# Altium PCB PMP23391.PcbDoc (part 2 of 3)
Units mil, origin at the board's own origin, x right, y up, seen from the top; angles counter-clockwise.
Board outline 5500 x 3250 mil, 2 copper layers (Top Layer, Bottom Layer), stack 62 mil thick; 163 components, 101 nets, 543 pads, 307 vias.
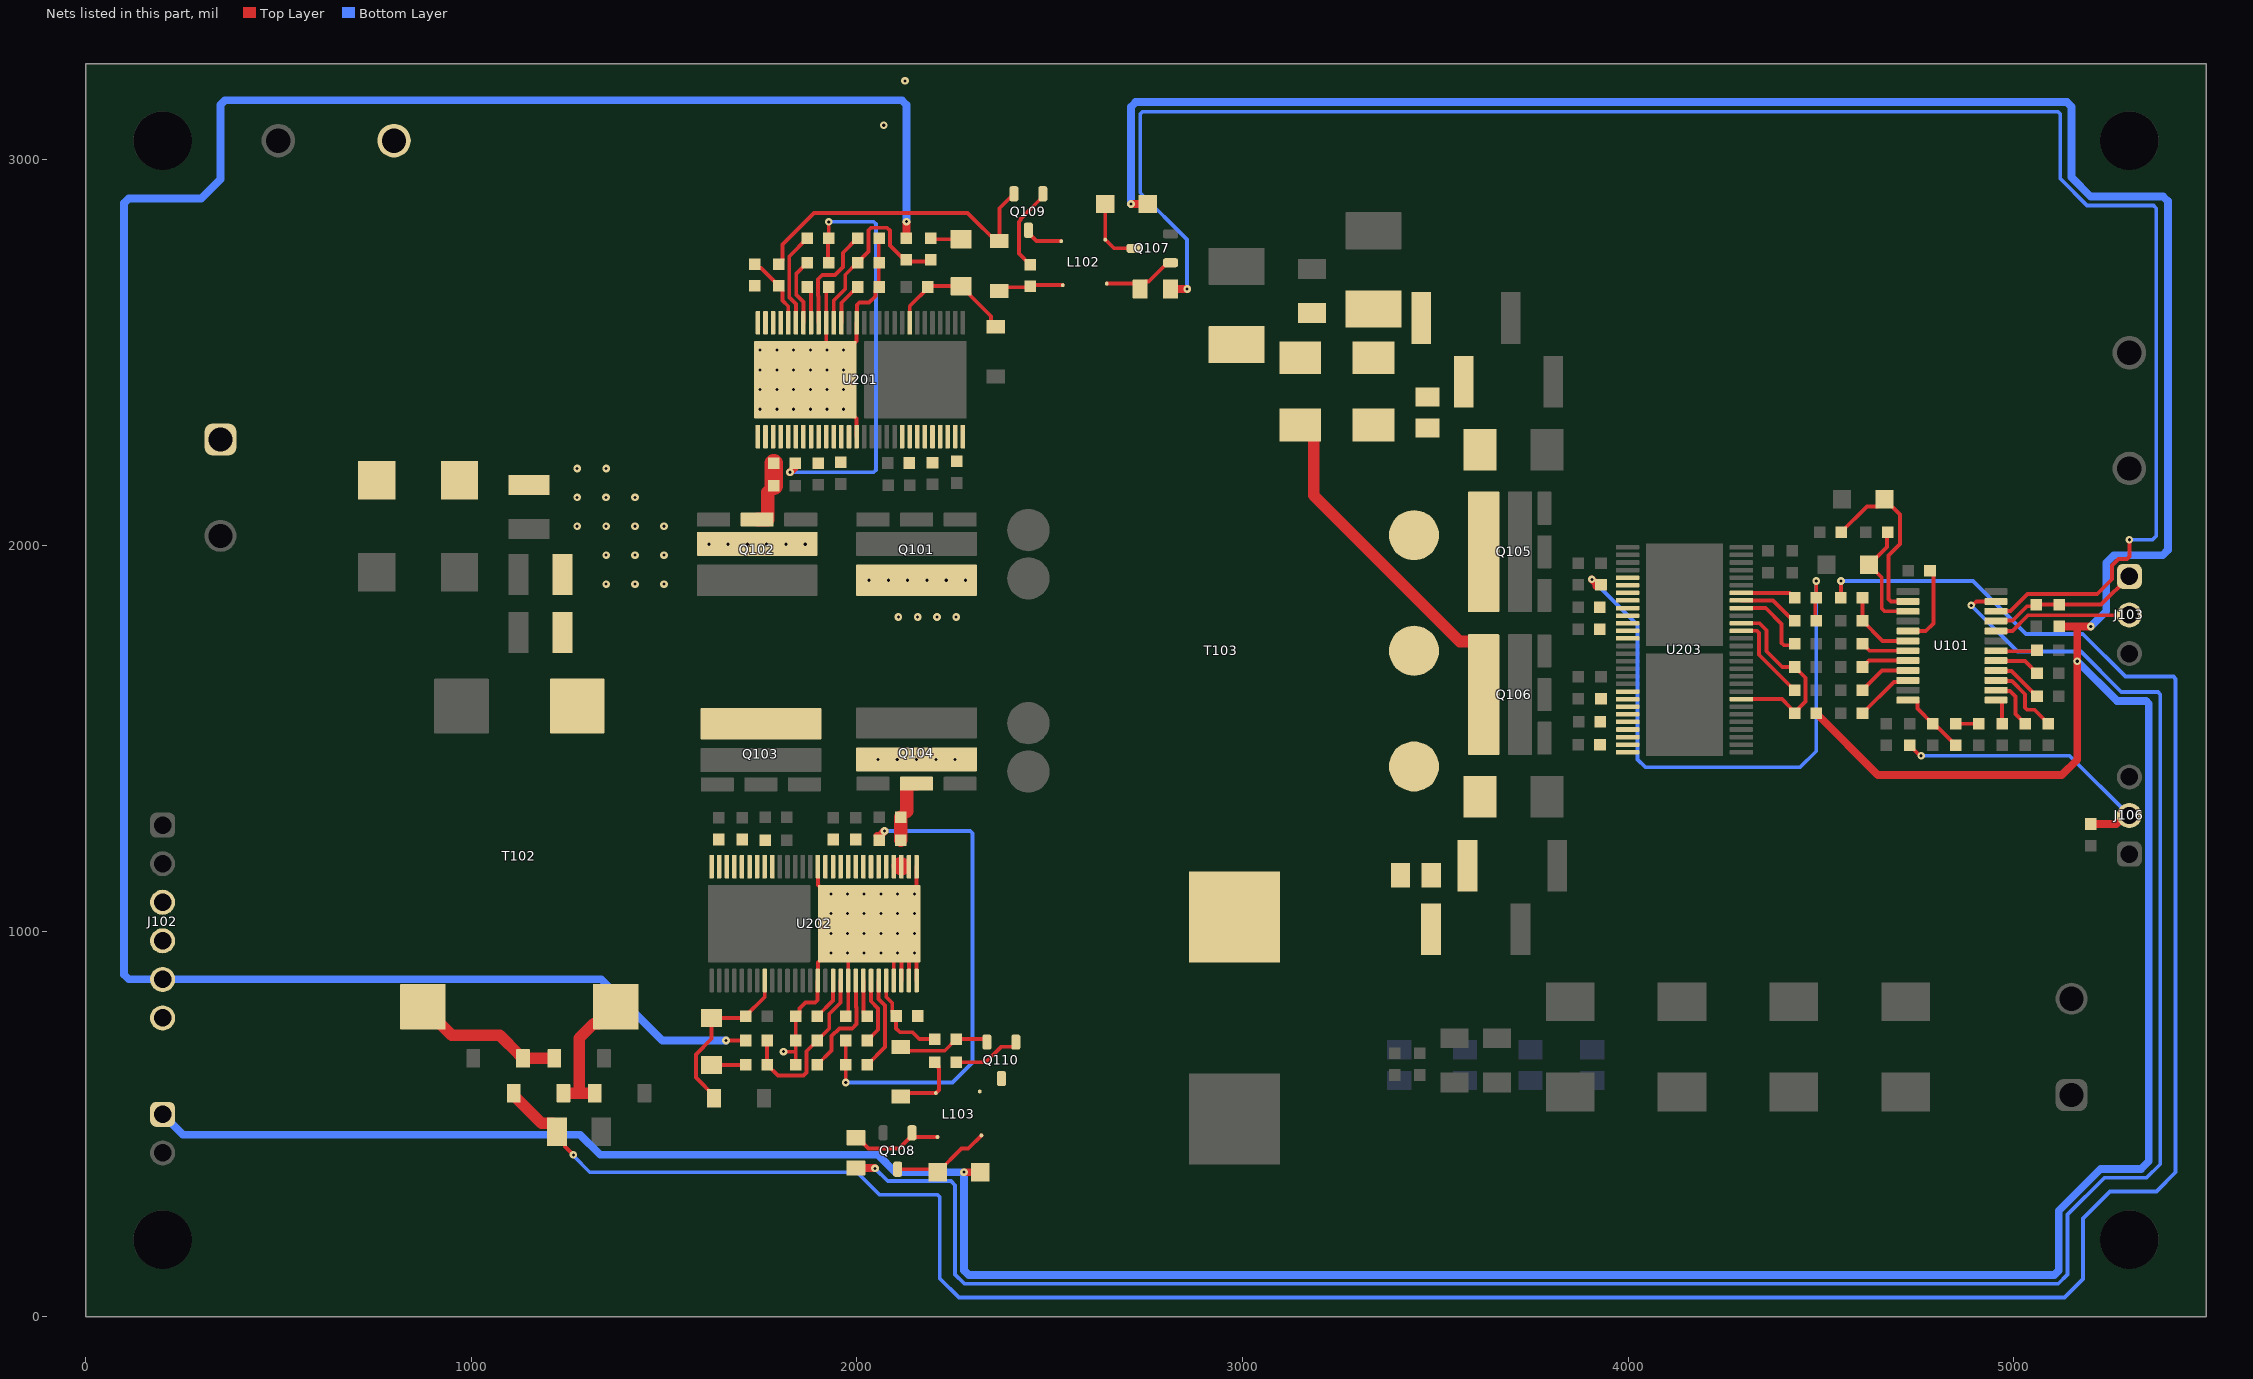
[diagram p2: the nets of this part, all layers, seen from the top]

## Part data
C101 C115 C116 C201 C202 C204 C206 C207 C209 C211 C212: library part CMP-0007405-5, "CAP, CERM, 1 uF, 25 V, +/- 10%, X7R, 0603", Cap_Case=0603, Manufacturer=MuRata, Supplier Part Number 1=490-5307-1-ND, TempCo=X7R, Tolerance_%=10%, Value1=Unknown, Value2=25V, ValueDisplayed=1uF
C102 C103: library part CMP-0011753-2, "CAP, TA, 22 uF, 50 V, +/- 10%, 0.5 ohm, SMD", Cap_Case=7343-43, Manufacturer=Kemet, Supplier Part Number 1=399-10275-1-ND, Tolerance_%=10%, Value1="0.5 ohm", Value2=50V, ValueDisplayed=22uF
C104 C205 C210 C213 C214: library part CMP-0007499-4, "CAP, CERM, 2.2 uF, 16 V, +/- 10%, X7R, 0603", Cap_Case=0603, Manufacturer=MuRata, Supplier Part Number 1=81-GRM188Z71C225KE3D, TempCo=X7R, Tolerance_%=10%, Value1=Unknown, Value2=16V, ValueDisplayed=2.2uF
C105: library part CMP-0007425-5, "CAP, CERM, 5600 pF, 25 V, +/- 10%, X7R, 0603", Cap_Case=0603, Manufacturer=MuRata, Supplier Part Number 1=GRM188R71E562KA01D-ND, TempCo=X7R, Tolerance_%=10%, Value1=Unknown, Value2=25V, ValueDisplayed=5600pF
C106: library part CMP-0084679-1, "CAP, CERM, 0.1 µF, 25 V,+/- 10%, X7R, AEC-Q200 Grade 1, 0603", Cap_Case=0603, Manufacturer=MuRata, TempCo=X7R, Tolerance_%=10%, Value2=25V, ValueDisplayed=0.1µF
C107 C108: library part CMP-0860266-1, "CAP, CERM, 10 µF, 50 V,+/- 10%, X8L, AEC-Q200 Grade 0, 1210", Cap_Case=1210, Manufacturer=MuRata, TempCo=X8L, Tolerance_%=10%, Value2=50V, ValueDisplayed=10µF
C109: library part CMP-0007138-4, "CAP, CERM, 0.47 uF, 16 V, +/- 10%, X7R, AEC-Q200 Grade 1, 0603", Cap_Case=0603, Manufacturer=MuRata, Supplier Part Number 1=490-4775-1-ND, TempCo=X7R, Tolerance_%=10%, Value1=Unknown, Value2=16V, ValueDisplayed=0.47uF
C110: library part CMP-0084283-1, "CAP, CERM, 10 pF, 100 V,+/- 5%, C0G/NP0, AEC-Q200 Grade 1, 0603", Cap_Case=0603, Manufacturer=MuRata, TempCo=C0G/NP0, Tolerance_%=5%, Value2=100V, ValueDisplayed=10pF
C111: library part CMP-0007427-5, "CAP, CERM, 6800 pF, 25 V, +/- 10%, X7R, 0603", Cap_Case=0603, Manufacturer=MuRata, Supplier Part Number 1=81-GRM18R71E682KA01D, TempCo=X7R, Tolerance_%=10%, Value1=Unknown, Value2=25V, ValueDisplayed=6800pF
C112: library part CMP-0007179-4, "CAP, CERM, 120 pF, 50 V, +/- 5%, C0G/NP0, 0603", Cap_Case=0603, Manufacturer=MuRata, Supplier Part Number 1=490-1429-1-ND, TempCo=C0G/NP0, Tolerance_%=5%, Value1=Unknown, Value2=50V, ValueDisplayed=120pF
C113 C114 C305 C306: library part CMP-0007171-4, "CAP, CERM, 100 pF, 50 V, +/- 5%, C0G/NP0, 0603", Cap_Case=0603, Manufacturer=MuRata, Supplier Part Number 1=490-1427-1-ND, TempCo=C0G/NP0, Tolerance_%=5%, Value1=Unknown, Value2=50V, ValueDisplayed=100pF
C117 C118: library part CMP-0008098-2, "CAP, CERM, 1200 pF, 100 V, +/- 5%, C0G/NP0, 0805", Cap_Case=0805, Manufacturer=MuRata, Supplier Part Number 1=GRM2165C2A122JA01D-ND, TempCo=C0G/NP0, Tolerance_%=5%, Value1=Unknown, Value2=100V, ValueDisplayed=1200pF
C119 C120: library part CMP-0082252-1, "CAP, CERM, 10 µF, 25 V,+/- 20%, X7R, AEC-Q200 Grade 1, 1206", Cap_Case=1206, Manufacturer=MuRata, Supplier Part Number 1=490-6519-1-ND, TempCo=X7R, Tolerance_%=20%, Value2=25V, ValueDisplayed=10µF
C121 C123 C124 C125: library part CMP-0012041-2, "CAP, TA, 100 uF, 25 V, +/- 10%, 0.1 ohm, SMD", Cap_Case=V, Manufacturer=AVX, Supplier Part Number 1=478-3104-1-ND, Tolerance_%=10%, Value1="0.1 ohm", Value2=25V, ValueDisplayed=100uF
C122: library part CMP-0008881-2, "CAP, CERM, 0.1 uF, 100 V, +/- 10%, X7R, 1206", Cap_Case=1206, Manufacturer=MuRata, Supplier Part Number 1=490-3364-1-ND, TempCo=X7R, Tolerance_%=10%, Value1=Unknown, Value2=100V, ValueDisplayed=0.1uF
C203 C208: library part CMP-0079602-1, "CAP, CERM, 0.1 µF, 50 V,+/- 10%, X7R, AEC-Q200 Grade 1, 0603", Cap_Case=0603, Manufacturer=Kemet, Supplier Part Number 1=399-6856-1-ND, TempCo=X7R, Tolerance_%=10%, Value2=50V, ValueDisplayed=0.1µF
C301 C302 C303 C304: library part CMP-0008346-3, "CAP, CERM, 4.7 uF, 25 V, +/- 10%, X7R, 0805", Cap_Case=0805, Manufacturer=MuRata, Supplier Part Number 1=490-9962-1-ND, TempCo=X7R, Tolerance_%=10%, Value1=Unknown, Value2=25V, ValueDisplayed=4.7uF
D101 D102 D103 D104: library part CMP-0090343-1, "Diode Schottky 100V 250mA (DC) Surface Mount SOD-123", Digikey Part Number=1727-7326-1-ND, Forward Current=250mA, Manufacturer=Nexperia, Max Surge Forward Current=2.5A, Mouser Part Number=841-BAT46GWJ, Operating Temperature Range="to +150°C", Peak Reverse Current=2uA, ValueDisplayed=39pF
D105 D108 D111 D112: library part CMP-0080763-2, "Diode, Schottky, 40 V, 3 A, AEC-Q101, SOD-123W", Manufacturer=Nexperia, Value1=3A, Value2=0.54V
D106 D107 D109 D110: library part CMP-0028521-2, "Diode, Schottky, 100 V, 1 A, SMB", Manufacturer="ON Semiconductor", Value1=1A, Value2=0.75V
D113 D114: library part CMP-0076974-2, "Diode, Switching, 100 V, 0.15 A, SOD-123", Manufacturer="Micro Commercial Components", Value1=0.15A, Value2=1.25V
D201 D203: library part CMP-0095320-1, "Diode Schottky 200 V 1A Surface Mount SOD-123W", Digikey Part Number=SS1H20LWRVGCT-ND, Forward Current=1A, Manufacturer="Taiwan Semiconductor", Max Surge Forward Current=30A, Mouser Part Number=821-SS1H20LW, Operating Temperature Range="-55°C to +175°C", Peak Reverse Current=0.1mA
D202 D204: library part CMP-0005752-4, "Diode, Zener, 13 V, 500 mW, SOD-123", Manufacturer="Diodes Inc.", Power_W=500mW, Value1=0.5W
H201 H202 H203 H204: library part CMP-0003690-1, Manufacturer=Keystone, Supplier Part Number 1=36-4824-ND
J101 J105: library part CMP-0075360-1, "Terminal Block, 6.35mm, 2x1, TH", Color=Green, Current_A=30A, Manufacturer="On-Shore Technology", Supplier Part Number 1=ED2675-ND, Voltage_V=300V
J102: library part CMP-0054801-2, "Header, 2.54 mm, 6x1, Gold, TH", Color=Black, Manufacturer="Wurth Elektronik", Supplier Part Number 1=732-5319-ND
J103 J106: library part CMP-0054796-4, "Header, 2.54 mm, 3x1, Gold, TH", Manufacturer="Wurth Elektronik", Supplier Part Number 1=732-5316-ND
J104: library part CMP-0054794-2, "Header, 2.54 mm, 2x1, Gold, TH", Color=Black, Manufacturer="Wurth Elektronik", Supplier Part Number 1=732-5315-ND
L101: library part CMP-0064040-1, "Inductor, Shielded Drum Core, WE-Superflux200, 1.3 uH, 34.5 A, 0.0009 ohm, SMD", Manufacturer="Wurth Elektronik", Supplier Part Number 1=732-2168-1-ND, Value1="0.0009 ohm", Value2=34.5A, ValueDisplayed=1.3uH
L102 L103: library part CMP-0012812-2, "Coupled inductor, 22 uH, 0.7 A, 1.63 ohm, TH", Manufacturer=Coilcraft, Supplier Part Number 1=994-LPD4012-333MRB, ValueDisplayed=22uH
Logo101: library part CMP-0074837-2, "IEC 61010-1 Hot Surface Warning", Manufacturer="Texas Instruments"
Logo201: library part CMP-0074769-1
Logo202: library part CMP-0074847-1, "FCC_disclaimer"
Logo203: library part CMP-0074836-1, "IEC 61010-1 Caution Warning"
Q101 Q102 Q103 Q104 Q105 Q106: library part CMP-0047628-1, "MOSFET N-Channel 100 V 80A (Tc) Surface Mount 5-SMD", Digikey Part Number=4107-EPC7018GC-ND, Drain To Source Breakdown Voltage=100V, Input Capacitace At Vds="1240pF @ 50V", Manufacturer="EPC Space", Operating Temperature Range="-55°C to +150°C", Pulse Drain Current=345A
Q107 Q108: library part CMP-0000755-1, "MOSFET, N-CH, 50 V, 0.22 A, SOT-23", Alternate Manufacturer=None, Manufacturer="Fairchild Semiconductor", Supplier Part Number 1=BSS138CT-ND, Value2="1.7 nC"
Q109 Q110: library part CMP-0000331-2, "Transistor, PNP, 60 V, 0.8 A, SOT-23", Manufacturer="Fairchild Semiconductor", Supplier Part Number 1=MMBT2907AFSCT-ND, Value1="0.8 A", Value2=300
R101: library part CMP-0022052-4, "RES, 147 k, 1%, 0.1 W, AEC-Q200 Grade 0, 0603", Manufacturer=Vishay-Dale, Power_W=100mW, Supplier Part Number 1=541-147KHCT-ND, TempCo="100 ppm/C", Tolerance_%=1%, Value2=0.1W, Value_Code=147k
R102: library part CMP-0022589-4, "RES, 75.0 k, 1%, 0.1 W, AEC-Q200 Grade 0, 0603", Manufacturer=Vishay-Dale, Power_W=100mW, Supplier Part Number 1=541-75.0KHCT-ND, TempCo="100 ppm/C", Tolerance_%=1%, Value2=0.1W, Value_Code=75k0, ValueDisplayed=75.0k
R103: library part CMP-0016768-3, "RES, 1.69, 1%, 0.25 W, AEC-Q200 Grade 0, 1206", Manufacturer=Vishay-Dale, Power_W=250mW, Supplier Part Number 1=541-1.69FFCT-ND, TempCo="100 ppm/C", Tolerance_%=1%, Value2=0.25W, Value_Code=1R69, ValueDisplayed=1.69
R104 R230: library part CMP-0022447-4, "RES, 49.9 k, 1%, 0.1 W, AEC-Q200 Grade 0, 0603", Manufacturer=Vishay-Dale, Power_W=100mW, Supplier Part Number 1=541-49.9KHCT-ND, TempCo="100 ppm/C", Tolerance_%=1%, Value2=0.1W, Value_Code=49k9, ValueDisplayed=49.9k
R105: library part CMP-0022903-4, "RES, 205 k, 1%, 0.1 W, 0603", Manufacturer=Yageo, Power_W=100mW, Supplier Part Number 1=311-205KHRCT-ND, TempCo="100 ppm/C", Tolerance_%=1%, Value2=0.1W, Value_Code=205k
R106: library part CMP-0025736-4, "RES, 1.0 M, 5%, 0.1 W, AEC-Q200 Grade 0, 0603", Manufacturer=Vishay-Dale, Power_W=100mW, Supplier Part Number 1=541-1.0MGCT-ND, TempCo="200 ppm/C", Tolerance_%=5%, Value2=0.1W, Value_Code=1M00, ValueDisplayed=1.0M
R107 R109 R201 R202 R214 R216 R227 R229: library part CMP-0025697-4, "RES, 0, 5%, 0.1 W, AEC-Q200 Grade 0, 0603", Manufacturer=Vishay-Dale, Power_W=100mW, Supplier Part Number 1=541-0.0GCT-ND, TempCo="200 ppm/C", Tolerance_%=5%, Value2=0.1W, Value_Code=0000, ValueDisplayed=0
R108: library part CMP-0015178-2, "RES, 0.3, 1%, 0.5 W, 1210", Manufacturer=Rohm, Power_W=500mW, Supplier Part Number 1=RHM.30SCT-ND, TempCo="200 ppm/C", Tolerance_%=1%, Value2=0.5W, Value_Code=R300, ValueDisplayed=0.3
R110: library part CMP-0022347-4, "RES, 34.8 k, 1%, 0.1 W, AEC-Q200 Grade 0, 0603", Manufacturer=Vishay-Dale, Power_W=100mW, Supplier Part Number 1=541-34.8KHCT-ND, TempCo="100 ppm/C", Tolerance_%=1%, Value2=0.1W, Value_Code=34k8, ValueDisplayed=34.8k
R111: library part CMP-0022126-4, "RES, 1.50 k, 1%, 0.1 W, AEC-Q200 Grade 0, 0603", Manufacturer=Vishay-Dale, Power_W=100mW, Supplier Part Number 1=541-1.50KHCT-ND, TempCo="100 ppm/C", Tolerance_%=1%, Value2=0.1W, Value_Code=1k50, ValueDisplayed=1.50k
R112: library part CMP-0022324-4, "RES, 30.1 k, 1%, 0.1 W, AEC-Q200 Grade 0, 0603", Manufacturer=Vishay-Dale, Power_W=100mW, Supplier Part Number 1=541-30.1KHCT-ND, TempCo="100 ppm/C", Tolerance_%=1%, Value2=0.1W, Value_Code=30k1, ValueDisplayed=30.1k
R113 R114 R204 R217: library part CMP-0025700-4, "RES, 100, 5%, 0.1 W, AEC-Q200 Grade 0, 0603", Manufacturer=Vishay-Dale, Power_W=100mW, Supplier Part Number 1=541-100GCT-ND, TempCo="200 ppm/C", Tolerance_%=5%, Value2=0.1W, Value_Code=100R, ValueDisplayed=100
R115 R116: library part CMP-0020803-2, "RES, 0, 5%, 0.125 W, 0805", Manufacturer="Yageo America", Power_W=125mW, Supplier Part Number 1=311-0.0ARCT-ND, TempCo="200 ppm/C", Tolerance_%=5%, Value2=0.125W, Value_Code=0000, ValueDisplayed=0
R117 R118 R119 R120: library part CMP-0015945-3, "RES, 33, 5%, 1 W, AEC-Q200 Grade 0, 2512", Manufacturer=Vishay-Dale, Power_W=1W, Supplier Part Number 1=541-33XCT-ND, TempCo="200 ppm/C", Tolerance_%=5%, Value_Code=33R0, ValueDisplayed=33
R121 R301: library part CMP-0122385-1, "10 kOhms ±1% 2W Chip Resistor 2512 (6432 Metric) Current Sense Thick Film", Digikey Part Number=118-CRM2512-FX-1002ELFCT-ND, Manufacturer=Bourns, Mouser Part Number=652-CRM2512FX1002ELF, Operating Temperature Range="-55°C to +155°C", Power_W=2W, TempCo=100ppm/°C, Tolerance_%=1%
R122 R123 R206 R212 R213 R219 R225 R226 R228 R235 R236: library part CMP-0021998-4, "RES, 10.0 k, 1%, 0.1 W, AEC-Q200 Grade 0, 0603", Manufacturer=Vishay-Dale, Power_W=100mW, Supplier Part Number 1=541-10.0KHCT-ND, TempCo="100 ppm/C", Tolerance_%=1%, Value2=0.1W, Value_Code=10k0, ValueDisplayed=10.0k
R124: library part CMP-0022003-4, "RES, 10.0, 1%, 0.1 W, AEC-Q200 Grade 0, 0603", Manufacturer=Vishay-Dale, Power_W=100mW, Supplier Part Number 1=541-10.0HCT-ND, TempCo="100 ppm/C", Tolerance_%=1%, Value2=0.1W, Value_Code=10R0, ValueDisplayed=10.0
R125: library part CMP-0022012-4, "RES, 115 k, 1%, 0.1 W, AEC-Q200 Grade 0, 0603", Manufacturer=Vishay-Dale, Power_W=100mW, Supplier Part Number 1=541-115KHCT-ND, TempCo="100 ppm/C", Tolerance_%=1%, Value2=0.1W, Value_Code=115k
R126: library part CMP-0022559-4, "RES, 6.19 k, 1%, 0.1 W, AEC-Q200 Grade 0, 0603", Manufacturer=Vishay-Dale, Power_W=100mW, Supplier Part Number 1=541-6.19KHCT-ND, TempCo="100 ppm/C", Tolerance_%=1%, Value2=0.1W, Value_Code=6k19, ValueDisplayed=6.19k
R203 R205 R215 R218: library part CMP-0021990-4, "RES, 100 k, 1%, 0.1 W, AEC-Q200 Grade 0, 0603", Manufacturer=Vishay-Dale, Power_W=100mW, Supplier Part Number 1=541-100KHCT-ND, TempCo="100 ppm/C", Tolerance_%=1%, Value2=0.1W, Value_Code=100k
R207 R220: library part CMP-0022732-2, "RES, 2.00, 1%, 0.125 W, 0603", Manufacturer=Vishay/Beyschlag, Power_W=125mW, Supplier Part Number 1=MCT06030C2008FP500-ND, TempCo="50 ppm/C", Tolerance_%=1%, Value2=0.125W, Value_Code=2R00, ValueDisplayed=2.00
R208 R209 R210 R211 R221 R222 R223 R224 R231 R232 R233 R234: library part CMP-0022311-4, "RES, 2.49, 1%, 0.1 W, AEC-Q200 Grade 0, 0603", Manufacturer=Vishay-Dale, Power_W=100mW, Supplier Part Number 1=541-2.49HHCT-ND, TempCo="100 ppm/C", Tolerance_%=1%, Value2=0.1W, Value_Code=2R49, ValueDisplayed=2.49
T102: library part CMP-0122471-1, "Current Transformer 1:50", Manufacturer="Payton Planar", Operating Temperature Range=to
T103: library part CMP-0122726-1, "Transformer Vin-22-36V/500KHz/Full-Bridge, Vo=12V/26A Isolation=1500V, T/R=3:2", Manufacturer=Coilcraft, Operating Temperature Range=to, Voltage_Isolation_Vrms=1.5kV
TP101 TP103: library part CMP-0055147-2, "Test Point, Multipurpose, Red, TH", Color=Red, Manufacturer="Keystone Electronics", Supplier Part Number 1=36-5010-ND
TP102 TP104: library part CMP-0055148-2, "Test Point, Multipurpose, Black, TH", Color=Black, Manufacturer="Keystone Electronics", Supplier Part Number 1=36-5011-ND
U101: library part CMP-0092938-1, Manufacturer="Texas Instruments", Operating Temperature Range=to
U201 U202 U203: library part CMP-0120202-4, Manufacturer="Texas Instruments", Operating Temperature Range=to

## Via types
v1: diameter 20, hole 8, Top Layer to Bottom Layer, 211 vias
v2: diameter 19.68, hole 7.87, Top Layer to Bottom Layer, tented both sides, 96 vias

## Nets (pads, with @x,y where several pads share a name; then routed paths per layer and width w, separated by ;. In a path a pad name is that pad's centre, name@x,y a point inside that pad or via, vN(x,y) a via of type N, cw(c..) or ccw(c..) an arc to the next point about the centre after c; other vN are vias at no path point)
+12Vp: J102.5 R201.1 R214.1 | length 6287.4
  Top Layer w10: v1(1660.91,716.59) R214.1@1711.65,716.59
  Top Layer w20: R201.1@2128.76,2796.84 v1(2128.76,2839.87)
  Bottom Layer w20: v1(1660.91,716.59) 1496.05,716.59 1337.64,875 J102.5@200,875 111.72,875 100,886.72 100,2888.28 111.72,2900 300,2900 350,2950 350,3143.28 361.72,3155 2117.04,3155 2128.76,3143.28 v1(2128.76,2839.87)
+12Vs: D111.1 D112.1 J104.1 R107.2 R227.1 | length 12792.8
  Top Layer w20: v1(2278.28,375) D112.1@2320.12,375 ; v1(2711.3,2885.7) D111.1@2754.33,2885.7 ; R227.1@4488,1565 4648,1405 5125,1405 5165,1445 v1(5165,1700) 5165,1790 ; R107.2@5119.48,1790 5165,1790 ; v1(5200,1790) 5165,1790
  Bottom Layer w20: J104.1@200,525 252.79,472.21 1282.21,472.21 1334.42,420 2055,420 2100,375 v1(2278.28,375) 2278.28,120.18 2289.99,108.46 5105.41,108.46 5117.13,120.18 5117.13,274.81 5225.78,383.46 5330.49,383.46 5350.35,403.32 5350.35,1590.06 5343.28,1597.13 5267.87,1597.13 v1(5165,1700) ; v1(2711.3,2885.7) 2711.3,3138.28 2723.01,3150 5138.28,3150 5150,3138.28 5150,2955 5200,2905 5388.28,2905 5400,2893.28 5400,1988.56 5386.44,1975 5260,1975 5240,1955 5240,1830 v1(5200,1790)
NetC101_1: C101.1 J103.1 R107.1 U101.9 | length 395.8
  Top Layer w10: U101.9@4952.77,1802.86 4955.71,1805.8 4997.62,1805.8 5034.45,1842.64 5054.35,1842.64 C101.1@5058.6,1846.89 R107.1@5118.6,1846.89 5226.89,1846.89 J103.1@5300,1920
NetC104_2: C104.2 U101.17 | length 214.9
  Top Layer w10: U101.17@4725.83,1778.39 4772.14,1778.39 4792,1798.24 4792,1926 C104.2@4783,1935
NetC105_2: C105.2 U101.5 | length 120.9
  Top Layer w10: U101.5@4952.77,1700.5 5028.98,1700.5 C105.2@5060.6,1668.89
NetC106_1: C106.1 U101.22 | length 153.2
  Top Layer w9.84: C106.1@4608,1565 4689.5,1646.5 4721.89,1646.5 U101.22@4725.83,1650.43
NetC109_2: C109.2 U101.20 | length 124.7
  Top Layer w10: C109.2@4608,1685 4624.61,1701.61 U101.20@4725.83,1701.61
NetC110_1: C110.1 R111.1 U101.18 | length 199.5
  Top Layer w10: R111.1@4608,1865 C110.1@4608,1805 4660.2,1752.8 U101.18@4725.83,1752.8
NetC111_1: C111.1 R112.1 | length 60
  Top Layer w10: R112.1@4850,1538 C111.1@4910,1538
NetC112_1: C112.1 R112.2 U101.24 | length 183.1
  Top Layer w10: U101.24@4725.83,1599.25 4746.5,1599.25 4750.35,1595.39 4750.35,1577.65 C112.1@4790,1538 4800,1528 4804,1528 R112.2@4850,1482
NetC117_1: C117.1 D106.1 D109.2 Q105.3 T103.11
NetC117_2: C117.2 R117.2 R119.2
NetC118_1: C118.1 D107.1 D110.2 Q106.3 T103.7 | length 922.1
  Top Layer w30: D110.2@3150,2312.99 3157.5,2312.99 3185,2285.49 3185,2130 3563.8,1751.2 3600.2,1751.2 3625.69,1725.7 Q106.3@3625.69,1613.64
NetC118_2: C118.2 R118.2 R120.2
NetC122_1: C122.1 D109.1 D110.1 R121.1 R301.1
NetC201_1: C201.1 R201.2 R207.1 U201.18 | length 499.6
  Top Layer w10: U201.18@1940.43,2577.89 1940.43,2635.55 1969.96,2665.07 1969.96,2702.35 2001.02,2733.41 C201.1@2002.33,2733.41 2012.33,2743.41 2012.33,2744.72 2030.2,2762.59 2030.2,2817.79 2036.68,2824.27 2078.66,2824.27 2086.2,2816.73 2086.2,2778.14 2127.44,2736.9 R207.1@2190.43,2736.9
NetC202_2: C202.2 U201.17 | length 109.5
  Top Layer w9.84: U201.17@1960.12,2577.89 1960.12,2629.52 C202.2@2001.02,2670.41
NetC203_1: C203.1 D201.1 D202.1 U201.8 | length 340.6
  Top Layer w10: U201.8@2137.28,2577.89 2137.28,2620.76 2186.94,2670.41 2189.4,2672.87 D201.1@2269.17,2672.87 ; D201.1@2270.49,2672.38 2274.42,2672.38 2293.05,2653.76 2293.05,2649.82 2348.24,2594.63 2348.24,2579.24 D202.1@2360,2567.48
NetC204_1: C204.1 U201.48 U201.49 U201.50
NetC205_2: C205.2 R202.1 R206.2 U201.33 U201.34 U201.35 | length 1113.5
  Top Layer w10: R202.1@1925,2796.84 1925,2735.5 R206.2@1927.09,2733.41 ; R202.1@1927.22,2796.4 v1(1927.22,2839.56)
  Top Layer w20: v1(1826.74,2190.1) C205.2@1839.02,2202.38
  Bottom Layer w10: v1(1826.74,2190.1) 2044.14,2190.1 2050,2195.96 2050,2833.7 2044.14,2839.56 v1(1927.22,2839.56)
NetC206_1: C206.1 R214.2 R220.1 U202.18 | length 455
  Top Layer w10: R214.2@1767.65,716.59 R220.1@1767.65,653.6 1795.52,625.73 1861.9,625.73 1869.69,633.52 1869.69,688.72 C206.1@1897.57,716.59 1928.62,747.65 1928.62,784.93 1958.15,814.45 U202.18@1958.15,872.11
NetC207_2: C207.2 U202.17 | length 109.5
  Top Layer w9.84: C207.2@1897.57,779.59 1938.46,820.48 U202.17@1938.46,872.11
NetC208_1: C208.1 D203.1 D204.1 U202.8 | length 446.9
  Top Layer w10: D204.1@1630.13,567.33 1630.13,573.33 1583.07,620.39 1583.07,680.62 1623.5,721.06 D203.1@1623.5,774.82 1706.88,774.82 C208.1@1711.65,779.59 1761.3,829.24 U202.8@1761.3,872.11
NetC209_1: C209.1 U202.48 U202.49 U202.50
NetC210_2: C210.2 R216.1 R219.2 U202.33 U202.34 U202.35 | length 1307.1
  Top Layer w10: v1(1971.49,607.62) R216.1@1971.49,653.6 R219.2@1971.49,716.59
  Top Layer w20: C210.2@2053.98,1247.62 2059.56,1247.62 v1(2071.84,1259.9)
  Bottom Layer w10: v1(1971.49,607.62) 2248.16,607.62 2300,659.46 2300,1254.04 2294.14,1259.9 v1(2071.84,1259.9)
NetC211_1: C211.1 R227.2 U203.8 U203.18 | length 525
  Top Layer w10: U203.8@4294.02,1601.75 4399.09,1601.75 4422,1578.84 4422,1575 4435.01,1561.99 4438.85,1561.99 4438.85,1574.3 4441.3,1574.3 4442,1575 4442,1577.45 4459.87,1595.32 4459.87,1657.13 C211.1@4432,1685 4400,1685 4358.98,1726.02 4358.98,1780.22 4340.6,1798.6 U203.18@4294.02,1798.6
NetC212_2: C212.2 U203.17 | length 234.6
  Top Layer w9.84: U203.17@4294.02,1778.92 4334.19,1778.92 4339.96,1773.15 4339.96,1717.04 C212.2@4432,1625
NetC213_2: C213.2 U203.48 U203.49 U203.50
NetC214_2: C214.2 R228.2 R229.1 U203.33 U203.34 U203.35 | length 1575.8
  Top Layer w9.84: R229.1@4485.4,1804.51 R228.2@4485.4,1867.5 ; R228.2@4488,1865 v1(4488,1908.21)
  Top Layer w20: v1(3906.22,1912.29) 3918.5,1900.01 C214.2@3918.5,1894.43
  Bottom Layer w10: v1(3906.22,1912.29) 4024.33,1794.18 4024.33,1445.67 4045,1425 4446.42,1425 4488,1466.58 v1(4488,1908.21)
NetC305_2: C305.2 R204.1 U201.24 | length 188.3
  Top Layer w10: C305.2@1735,2729.91 1745,2719.91 1751.17,2719.91 R204.1@1797.17,2673.91 ; R204.1@1797.17,2670.41 1807.17,2660.41 1807.17,2635.57 1822.32,2620.42 U201.24@1822.32,2577.89
NetC306_2: C306.2 R217.1 U202.24 | length 246.6
  Top Layer w10: U202.24@2076.26,872.11 2076.26,829.58 2092,813.84 2092,790 C306.2@2102,780 2102,747.62 2111.69,737.93 2144.07,737.93 2162,720 R217.1@2202,720
NetD101_2: D101.2 D103.1 T102.3 | length 399.8
  Top Layer w30: T102.3@875,804.33 949.33,730 1074.37,730 1125.35,679.02 1131.46,679.02 1134.37,676.1 D101.2@1134.37,670 D103.1@1215.63,670
NetD102_1: D102.1 R103.2 R111.2 | length 7196.6
  Top Layer w9.84: R111.2@4552,1865 v1(4552,1908.21)
  Top Layer w10: R103.2@1222.91,480 1243.5,459.41 1243.5,441.5 v1(1265,420)
  Top Layer w30: D102.1@1110.63,580 1110.63,573.9 1183.11,501.42 1212.32,501.42 1222.91,490.83 R103.2@1222.91,480
  Bottom Layer w10: v1(1265,420) 1265,417.65 1307.65,375 2000.1,375 2058.56,316.54 2209.14,316.54 2215,310.68 2215,99.67 2264.67,50 5132.2,50 5180,97.8 5180,255 5250,325 5370,325 5420,375 5420,1654.14 5414.14,1660 5290,1660 5180,1770 5179.32,1770.68 5031.67,1770.68 4894.14,1908.21 v1(4552,1908.21)
NetD102_2: D102.2 D104.1 T102.4 | length 376.4
  Top Layer w30: D102.2@1239.37,580 1280,580 ; D104.1@1320.63,580 1280,580 ; T102.4@1382.06,824.9 1382.06,811.39 1330.94,760.28 1317.44,760.28 1280,722.84 1280,580
NetD105_2: D105.2 R113.2 U101.14 | length 487.4
  Top Layer w10: R113.2@4553,2035 4619.38,2101.38 4646.5,2101.38 D105.2@4665.12,2120 4705,2080.12 4705,2003.61 4675.76,1974.37 4675.76,1861.02 4681.61,1855.16 U101.14@4725.83,1855.16
NetD108_2: D108.2 R114.2 U101.15 | length 302.7
  Top Layer w10: R114.2@4673,2035 4671.31,2033.31 4671.31,1996.19 D108.2@4625.12,1950 4657.88,1917.24 4657.88,1836.57 4664.88,1829.57 U101.15@4725.83,1829.57
NetD111_2: D111.2 L102.2 Q107.3 | length 176.6
  Top Layer w10: D111.2@2644.09,2885.7 2644.21,2885.59 L102.2@2644.21,2793.33 2666.72,2770.82 Q107.3@2719.09,2770.82
NetD112_2: D112.2 L103.2 Q108.3 | length 259.9
  Top Layer w10: Q108.3@2105.79,382.76 2202.13,382.76 D112.2@2209.88,375 2271.21,436.33 2289,436.33 L103.2@2323,470.33
NetD113_2: D113.2 L102.4 R122.2 | length 166.5
  Top Layer w10: D113.2@2370,2669.76 2450,2669.76 2455.57,2675.33 L102.4@2534.21,2675.33
NetD114_2: D114.2 L103.4 R123.2 | length 178.6
  Top Layer w10: D114.2@2114.1,580.33 L103.4@2205,580.33 2213.25,588.58 2213.25,644.14 2212,645.39 2212,650 R123.2@2202,660
NetD201_2: D201.2 R207.2 | length 79.7
  Top Layer w10: R207.2@2191.75,2796.84 2194.16,2794.43 D201.2@2270.49,2794.43
NetD203_2: D203.2 R220.2 | length 88.5
  Top Layer w10: D203.2@1623.5,652.78 1710.82,652.78 R220.2@1711.65,653.6
NetJ103_2: J103.2 U101.8 | length 363.1
  Top Layer w9.84: U101.8@4954.17,1778.39 4996.82,1778.39 5037.53,1819.09 5299.09,1819.09 J103.2@5300,1820
NetJ106_2: J106.2 R124.1 R125.2 | length 754.5
  Top Layer w9.84: R125.2@4730,1482 4755.06,1456.94 4758.06,1456.94 v1(4760,1455)
  Top Layer w20: R124.1@5200,1278 5265.83,1278 5287.83,1300 J106.2@5300,1300
  Bottom Layer w9.84: v1(4760,1455) 5145,1455 J106.2@5300,1300
NetL101_1: L101.1 T103.9
NetL102_1: L102.1 Q107.1 R115.1 | length 195.4
  Top Layer w10: L102.1@2648.21,2679.33 2725.65,2679.33 2734.84,2670.14 2749.53,2684.82 2757.11,2684.82 2805.71,2733.42 Q107.1@2813.58,2733.42
NetL103_1: L103.1 Q108.1 R116.1 | length 247.2
  Top Layer w10: R116.1@1997.5,464.37 2002.42,464.37 2030.46,436.33 2109.66,436.33 2143.19,469.86 Q108.1@2143.19,477.24 ; Q108.1@2143.19,473.07 2149.93,466.33 L103.1@2209,466.33
NetQ101_3: Q101.3 Q103.3 R108.2 T102.1
  other v1: 2107.76,1815 2157.76,1815 2207.76,1815 2257.76,1815 2031.92,1910 2081.92,1910 2131.92,1910 2181.92,1910 2231.92,1910 2281.92,1910
NetQ109_1: Q109.1 R122.1 | length 222.4
  Top Layer w10: R122.1@2450,2727.88 2420.32,2757.57 2420.32,2839.31 2425,2844 2425,2846.97 2482.4,2904.37 Q109.1@2482.4,2912.24
NetQ110_1: Q110.1 R123.1 | length 179.2
  Top Layer w10: R123.1@2258,660 2334,660 2374.14,700.14 2405.66,700.14 2412.4,706.88 Q110.1@2412.4,712.24
NetR101_2: R101.2 U101.2 | length 138.4
  Top Layer w10: U101.2@4953.47,1623.03 4990.52,1623.03 5005,1608.55 5005,1563 R101.2@5030,1538
NetR102_2: R102.2 U101.3 | length 202.1
  Top Layer w10: U101.3@4953.77,1648.32 4995.23,1648.32 5028.98,1614.57 5028.98,1580.16 5034.84,1574.3 5053.7,1574.3 R102.2@5090,1538
NetR104_1: R104.1 U101.4 | length 135.2
  Top Layer w10: U101.4@4952.77,1674.91 4994.57,1674.91 R104.1@5060.6,1608.89
NetR105_1: R105.1 U101.1 | length 74.8
  Top Layer w10: U101.1@4954.17,1599.25 4966.14,1599.25 4970,1595.39 R105.1@4970,1538
NetR106_2: R106.2 U101.6 | length 109
  Top Layer w10: U101.6@4952.77,1726.09 5057.8,1726.09 R106.2@5060.6,1728.89
NetR109_1: R109.1 U101.19 | length 125.2
  Top Layer w10: R109.1@4608,1745 4625.8,1727.2 U101.19@4725.83,1727.2
NetR110_1: R110.1 U101.21 | length 139
  Top Layer w10: R110.1@4608,1625 4659.02,1676.02 U101.21@4725.83,1676.02
NetR115_2: R115.2 U101.10 | length 4779.1
  Top Layer w10: U101.10@4954.17,1829.57 4955.23,1830.62 4991.58,1830.62 5035.72,1874.76 5216.76,1874.76 5254.65,1912.65 5254.65,1948.3 5271.7,1965.35 5294.14,1965.35 5300,1971.21 v1(5300,2015)
  Top Layer w20: R115.2@2813.58,2665.22 v1(2856.61,2665.22)
  Bottom Layer w10: v1(2856.61,2665.22) 2856.61,2793.39 2735,2915 2735,3119.14 2740.86,3125 5114.91,3125 5120.77,3119.14 5120.77,2951.88 5190.53,2882.13 5362.36,2882.13 5369.74,2874.74 5369.74,2024.74 5360,2015 v1(5300,2015)
NetR116_2: R116.2 U101.11 | length 5731.6
  Top Layer w10: v1(4890,1845) 4892.71,1845 4902.86,1855.16 U101.11@4951.66,1855.16
  Top Layer w20: R116.2@1997.5,385.63 2046.87,385.63 v1(2047.5,385)
  Bottom Layer w10: v1(2047.5,385) 2080.37,352.13 2244.14,352.13 2255,341.27 2255,110 2279.41,85.59 5115.59,85.59 5140,110 5140,265.33 5235.26,360.59 5344.82,360.59 5380,395.77 5380,1614.14 5374.14,1620 5280,1620 5277.8,1622.2 5277.46,1622.2 5174.67,1725 5010,1725 v1(4890,1845)
NetR202_2: R202.2 U201.23 | length 244.7
  Top Layer w10: U201.23@1842.01,2577.89 1842.01,2626.02 1825.05,2642.98 1825.05,2750.22 R202.2@1871.22,2796.4
NetR203_2: R203.2 U201.21 | length 96.8
  Top Layer w10: R203.2@1871.09,2670.41 1881.09,2660.41 1881.09,2632.05 1881.38,2631.77 U201.21@1881.38,2577.89
NetR205_2: R205.2 U201.20 | length 281
  Top Layer w10: U201.20@1901.06,2577.89 1901.06,2646.15 1899.22,2648 1899.22,2690.75 1910.38,2701.91 1943.8,2701.91 1964.06,2722.16 1964.06,2759.44 R205.2@2001.02,2796.4
NetR206_1: R206.1 U201.22 | length 174.7
  Top Layer w10: U201.22@1861.69,2577.89 1861.69,2631.61 1843.22,2650.08 1843.22,2705.53 R206.1@1871.09,2733.41
NetR208_2: R208.2 U201.51 U201.52 U201.53
NetR209_2: R209.2 U201.54 U201.55 U201.56
NetR210_2: R210.2 U201.36 U201.37 U201.38
NetR211_2: R211.2 U201.39 U201.40 U201.41
NetR215_2: R215.2 U202.21 | length 96.8
  Top Layer w10: U202.21@2017.2,872.11 2017.2,818.23 2017.49,817.95 2017.49,789.59 R215.2@2027.49,779.59
NetR216_2: R216.2 U202.23 | length 244.6
  Top Layer w10: R216.2@2027.49,653.6 2073.54,699.65 2073.54,807.02 2056.57,823.98 U202.23@2056.57,872.11
NetR218_2: R218.2 U202.20 | length 281
  Top Layer w10: R218.2@1897.57,653.6 1934.53,690.56 1934.53,727.84 1954.78,748.09 1988.2,748.09 1999.36,759.25 1999.36,802 1997.52,803.85 U202.20@1997.52,872.11
NetR219_1: R219.1 U202.22 | length 174.7
  Top Layer w10: R219.1@2027.49,716.59 2055.36,744.47 2055.36,799.92 2036.89,818.39 U202.22@2036.89,872.11
NetR221_2: R221.2 U202.51 U202.52 U202.53
NetR222_2: R222.2 U202.54 U202.55 U202.56
NetR223_2: R223.2 U202.36 U202.37 U202.38
NetR224_2: R224.2 U202.39 U202.40 U202.41
NetR228_1: R228.1 U203.22 | length 139.5
  Top Layer w9.84: U203.22@4294.02,1877.34 4419.56,1877.34 R228.1@4429.4,1867.5
NetR229_2: R229.2 U203.21 | length 157.4
  Top Layer w9.84: U203.21@4294.02,1857.66 4376.25,1857.66 R229.2@4429.4,1804.51
NetR230_1: R230.1 U203.20 | length 204.2
  Top Layer w9.84: U203.20@4294.02,1837.97 4357.01,1837.97 4398.35,1796.63 4398.35,1747.28 4404.11,1741.51 R230.1@4429.4,1741.51
NetR231_2: R231.2 U203.51 U203.52 U203.53
NetR232_2: R232.2 U203.54 U203.55 U203.56
NetR233_2: R233.2 U203.36 U203.37 U203.38
NetR234_2: R234.2 U203.39 U203.40 U203.41
OUTA: D113.1 Q109.2 R204.2 | length 833.8
  Top Layer w10: R204.2@1797.17,2729.91 1807.17,2739.91 1807.17,2780.56 1889.36,2862.74 2287.26,2862.74 2370,2780 2370,2874.65 Q109.2@2407.6,2912.24
OUTB: D114.1 Q110.2 R217.2 | length 243.8
  Top Layer w10: D114.1@2114.1,699.91 2124.02,690 2228,690 R217.2@2258,720 2330.86,720 2337.6,713.26 Q110.2@2337.6,712.24
PGND: C102.2 C103.2 C107.2 C108.2 C201.2 C202.1 C205.1 C206.2 C207.1 C210.1 C305.1 C306.1 J101.1 J102.3 J102.4 J102.6 L102.3 L103.3 Q102.4 Q102.5 Q104.4 Q104.5 Q109.3 Q110.3 R203.1 R205.1 R213.2 R215.1 R218.1 R226.2 TP102.1 U201.15 U201.19 U201.25 U201.26 U201.27 U201.28 U201.29 U201.30 U201.31 U201.32 U201.42 U201.58 U202.15 U202.19 U202.25 U202.26 U202.27 U202.28 U202.29 U202.30 U202.31 U202.32 U202.42 U202.58 | length 2191.7
  Top Layer w10: v1(1810,687.5) 1841.34,687.5 ; 1841.57,687.73 C206.2@1841.57,716.59 C207.1@1841.57,779.59 1851.57,789.59 1851.57,799.72 1866.96,815.11 1892.33,815.11 1898.19,820.97 1898.19,871.2 U202.15@1899.09,872.11 1899.09,919.35 1922.72,942.97 v2(1932.56,942.97) ; R218.1@1841.71,653.75 1841.71,687.88 ; U202.42@1899.09,1167.38 1899.09,1120.14 1922.72,1096.52 v2(1932.56,1096.52) ; v2(1922.72,2507.03) 1920.75,2509 U201.19@1920.75,2577.89 1920.75,2664.07 R203.1@1927.09,2670.41 ; v2(1966.02,2353.48) 1975.87,2353.48 1999.49,2329.86 U201.42@1999.49,2282.62 ; v2(1966.02,2507.03) 1975.87,2507.03 1999.49,2530.65 U201.15@1999.49,2577.89 2000.39,2578.8 2000.39,2624.14 2006.25,2630 2031.92,2630 2048.33,2646.41 2048.33,2660.41 C202.1@2058.33,2670.41 ; R215.1@1971.49,779.59 1977.83,785.93 U202.19@1977.83,872.11 1977.83,941 v2(1975.87,942.97) ; U202.58@2031.97,1019.74 2037.19,1019.74 U202.58@2115.63,941.3 ; C202.1@2057.02,2670.41 R205.1@2057.02,2796.4 ; U202.25@2095.94,872.11 U202.58@2095.94,942.97 ; v2(2105.79,994.15) 2115.63,984.31 U202.58@2115.63,942.97 ; U202.26@2115.63,872.11 U202.58@2115.63,941.3 ; U202.27@2135.32,872.11 2135.32,921.62 U202.58@2115.63,941.3 ; v2(2149.09,942.97) 2155,937.07 U202.28@2155,872.11 ; v2(2149.09,1096.52) 2155,1102.42 U202.29@2155,1167.38 ; Q109.3@2445,2817.76 2445,2810.16 2465.82,2789.33 L102.3@2530.21,2789.33
  Top Layer w35.43: Q102.5@1743.58,2067.5 1768.58,2067.5 1768.86,2067.78 1768.86,2138.64 ; C210.1@2114.1,1236.28 R226.2@2114.1,1295.33 ; 2129.72,1311.36 2129.72,1382.22 2130,1382.5 Q104.5@2155,1382.5
  Top Layer w47.24: R213.2@1784.48,2154.67 C205.1@1784.48,2213.72 ; U202.31@2114.1,1168.91 U202.31@2115.63,1167.38
  other v1: 2055,1445.51 2105,1445.51 2155,1445.51 2205,1445.51 2255,1445.51 1350,1900 1425,1900 1500,1900 1350,1975 1425,1975 1500,1975 1616.39,2003.42 1666.39,2003.42 1716.39,2003.42 1766.39,2003.42 1816.39,2003.42 1866.39,2003.42 1275,2050 1350,2050 1425,2050 1500,2050 1275,2125 1349.69,2125 1425,2125 1275,2200 1350,2200 2070,3090 2125,3205
  other v2: 2019.17,942.97 2062.48,942.97 2105.79,942.97 1932.56,994.15 1975.87,994.15 2019.17,994.15 2062.48,994.15 2149.09,994.15 1932.56,1045.33 1975.87,1045.33 2019.17,1045.33 2062.48,1045.33 2105.79,1045.33 2149.09,1045.33 1975.87,1096.52 2019.17,1096.52 2062.48,1096.52 2105.79,1096.52 1749.49,2353.48 1792.8,2353.48 1836.1,2353.48 1879.41,2353.48 1922.72,2353.48 1749.49,2404.67 1792.8,2404.67 1836.1,2404.67 1879.41,2404.67 1922.72,2404.67 1966.02,2404.67 1749.49,2455.85 1792.8,2455.85 1836.1,2455.85 1879.41,2455.85 1922.72,2455.85 1966.02,2455.85 1749.49,2507.03 1792.8,2507.03 1836.1,2507.03 1879.41,2507.03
